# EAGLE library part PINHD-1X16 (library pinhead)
PIN HEADER
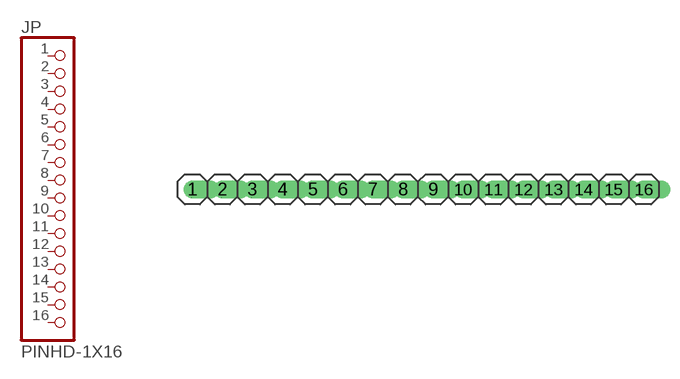
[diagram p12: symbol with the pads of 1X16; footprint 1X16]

Designator prefix JP

## PINHD-1X16  [1X16]
1  1  pas
2  2  pas
3  3  pas
4  4  pas
5  5  pas
6  6  pas
7  7  pas
8  8  pas
9  9  pas
10  10  pas
11  11  pas
12  12  pas
13  13  pas
14  14  pas
15  15  pas
16  16  pas

## Footprint 1X16 (pad centres in mm)
PIN HEADER
drill 1.016 offset: 1 -19.05,0; 2 -16.51,0; 3 -13.97,0; 4 -11.43,0; 5 -8.89,0; 6 -6.35,0; 7 -3.81,0; 8 -1.27,0; 9 1.27,0; 10 3.81,0; 11 6.35,0; 12 8.89,0; 13 11.43,0; 14 13.97,0; 15 16.51,0; 16 19.05,0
